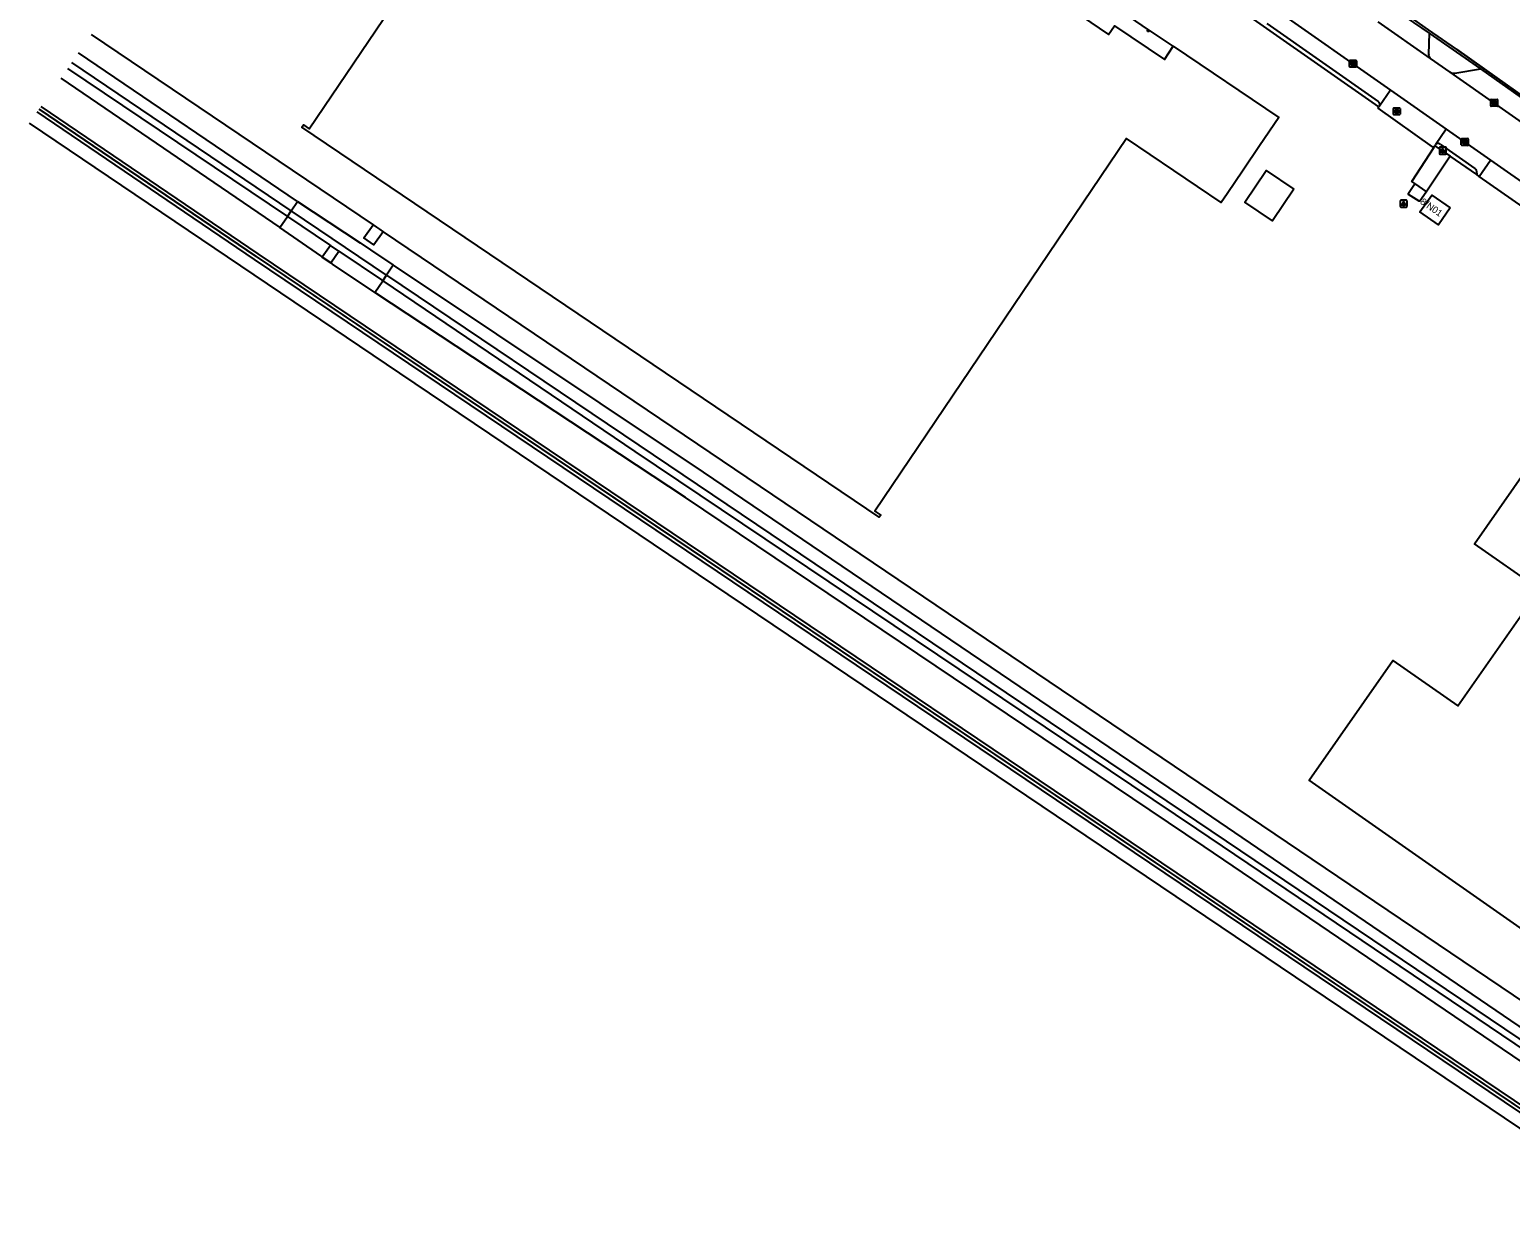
# Model space of a CAD drawing. Extents: x 155018 to 156648, y 383980 to 385733.
# Drawn here: x 155018.4 to 155235.9, y 384755.5 to 384931.8 of the extents above; entities that cross this region are included whole.
import ezdxf

# ---------------------------------------------------------------- set-up
doc = ezdxf.new("R2010")
doc.units = 0
for name, color, linetype in [('IMGEO_Brandkraan', 7, 'Continuous'), ('IMGEO_Groenvoorziening', 7, 'Continuous'), ('IMGEO_Hek', 7, 'Continuous'), ('IMGEO_Kademuur', 7, 'Continuous'), ('IMGEO_Kolk', 7, 'Continuous'), ('IMGEO_Lage_trafo', 7, 'Continuous'), ('IMGEO_Lichtpunt', 7, 'Continuous'), ('IMGEO_Oever', 7, 'Continuous'), ('IMGEO_Pand', 7, 'Continuous'), ('IMGEO_Pand_nummerreeks', 7, 'Continuous'), ('IMGEO_Pand_overbouw', 7, 'Continuous'), ('IMGEO_Parkeervlak_open', 7, 'Continuous'), ('IMGEO_Rijbaan_lokaal_gesloten', 7, 'Continuous'), ('IMGEO_Rijbaan_lokaal_open', 7, 'Continuous'), ('IMGEO_Terreindeel_onvherhard', 7, 'Continuous'), ('IMGEO_Voetpad_open', 7, 'Continuous'), ('IMGEO_Waterloop', 7, 'Continuous')]:
    doc.layers.add(name, color=color, linetype=linetype)

msp = doc.modelspace()

# ---------------------------------------------------------------- linework, layer by layer
at = {"layer": 'IMGEO_Brandkraan'}
for p, q in [((155218.71, 384919.32), (155218.71, 384920.18)), ((155218.78, 384920.25), (155219.64, 384920.25)), ((155219.2, 384920.03), (155219.22, 384920.03)), ((155219.71, 384920.18), (155219.71, 384919.32)), ((155219.64, 384919.25), (155218.78, 384919.25)), ((155219.22, 384919.47), (155219.2, 384919.47))]:
    msp.add_line(p, q, dxfattribs=at)
for points in [[(155218.71, 384919.32), (155218.71, 384920.18)], [(155218.78, 384920.25), (155219.64, 384920.25)], [(155219.06, 384919.95), (155219.06, 384919.55), (155219.27, 384919.55)], [(155219.29, 384919.95), (155219.06, 384919.95)], [(155219.24, 384919.87), (155219.18, 384919.87), (155219.18, 384919.79)], [(155219.71, 384920.18), (155219.71, 384919.32)], [(155219.64, 384919.25), (155218.78, 384919.25)], [(155219.18, 384919.79), (155219.24, 384919.79)], [(155219.25, 384919.72), (155219.18, 384919.72), (155219.18, 384919.64)], [(155219.18, 384919.64), (155219.25, 384919.64)]]:
    msp.add_lwpolyline(points, dxfattribs=at)
for centre, radius, start, end in [((155218.79, 384920.17), 0.0765, 91.552, 178.448), ((155218.79, 384920.17), 0.0765, 91.552, 178.448), ((155219.24, 384919.83), 0.0379, 267.8285, 90.9355), ((155219.29, 384919.8), 0.145, 59.4692, 91.5367), ((155219.32, 384919.85), 0.0922, 285.5137, 58.1501), ((155219.63, 384920.17), 0.0765, 1.552, 88.448), ((155219.63, 384920.17), 0.0765, 1.552, 88.448), ((155218.79, 384919.33), 0.0765, 181.552, 268.448), ((155218.79, 384919.33), 0.0765, 181.552, 268.448), ((155219.25, 384919.68), 0.0404, 269.8759, 90.5077), ((155219.28, 384919.8), 0.251, 268.6676, 293.5347), ((155219.32, 384919.66), 0.105, 301.3115, 78.989), ((155219.63, 384919.33), 0.0765, 271.552, 358.448), ((155219.63, 384919.33), 0.0765, 271.552, 358.448)]:
    msp.add_arc(centre, radius, start, end, dxfattribs=at)
for centre, major_axis, ratio, start_param, end_param in [((155219.2, 384919.75), (-0.387, 0.002), 0.722429, 4.712389, 7.853982), ((155219.22, 384919.75), (-0.39, 0.002), 0.717154, 1.570796, 4.712389)]:
    msp.add_ellipse(centre, major_axis=major_axis, ratio=ratio, start_param=start_param, end_param=end_param, dxfattribs=at)
at = {"layer": 'IMGEO_Groenvoorziening'}
for points in [[(155027.41, 384931.04), (155068.82, 384903.06)], [(155057.73, 384906.51), (155025.53, 384928.34)], [(155022.94, 384924.62), (155055.13, 384902.68)], [(155476.25, 384612.78), (155452.62, 384628.74), (155051.94, 384898.82), (155020.06, 384920.48)], [(155462.06, 384621.17), (155273.61, 384748.19), (155051.38, 384897.99), (155019.49, 384919.66)], [(155057.73, 384906.51), (155066.91, 384900.45), (155068.45, 384899.42), (155071.7, 384897.2), (155071.77, 384897.16)], [(155061.36, 384898.34), (155061.22, 384898.44), (155061.13, 384898.5), (155055.13, 384902.68)], [(155070.29, 384902.07), (155068.92, 384900.13), (155067.44, 384901.17), (155068.82, 384903.06)], [(155068.82, 384903.06), (155069.31, 384902.73), (155069.77, 384902.42), (155070.29, 384902.07)], [(155070.29, 384902.07), (155295.33, 384750), (155489.59, 384618.73)], [(155062.61, 384897.47), (155061.36, 384898.34)], [(155069.08, 384893.11), (155062.85, 384897.31), (155062.74, 384897.39), (155062.61, 384897.47)], [(155071.77, 384897.16), (155117.29, 384866.73), (155188.59, 384818.4), (155275.37, 384759.29), (155397.34, 384677)], [(155479.94, 384619.28), (155479.94, 384619.27), (155479.35, 384618.47), (155478.16, 384618.25), (155475.96, 384619.11), (155396.84, 384672.62), (155274.45, 384755.08), (155190.89, 384811.75), (155114.7, 384863.03), (155069.08, 384893.11)]]:
    msp.add_lwpolyline(points, dxfattribs=at)
at = {"layer": 'IMGEO_Hek'}
for points in [[(155227.99, 384928.88), (155232.07, 384925.99)], [(155232.07, 384925.99), (155247.24, 384915.22)], [(155051.66, 384898.4), (155019.78, 384920.07)], [(155224.48, 384914.55), (155216.48, 384920.23)], [(155051.66, 384898.4), (155112.43, 384857.45), (155113.3, 384856.85), (155273.89, 384748.61)]]:
    msp.add_lwpolyline(points, dxfattribs=at)
at = {"layer": 'IMGEO_Kademuur'}
msp.add_lwpolyline([(155062.55, 384900.04), (155061.36, 384898.34), (155062.61, 384897.47), (155063.81, 384899.19)], dxfattribs=at)
at = {"layer": 'IMGEO_Kolk'}
for p, q in [((155212.26, 384926.33), (155212.26, 384927.18)), ((155212.34, 384927.26), (155213.19, 384927.26)), ((155212.75, 384927.04), (155212.78, 384927.04)), ((155212.77, 384926.48), (155212.75, 384926.48)), ((155213.27, 384927.18), (155213.27, 384926.33)), ((155213.19, 384926.26), (155212.34, 384926.26)), ((155233.03, 384920.58), (155233.03, 384921.43)), ((155233.1, 384921.5), (155233.95, 384921.5)), ((155233.95, 384920.5), (155233.1, 384920.5)), ((155233.51, 384921.28), (155233.54, 384921.28)), ((155233.54, 384920.72), (155233.51, 384920.72)), ((155234.03, 384921.43), (155234.03, 384920.58)), ((155228.69, 384914.82), (155228.69, 384915.67)), ((155228.77, 384915.75), (155229.62, 384915.75)), ((155229.18, 384915.53), (155229.2, 384915.53)), ((155229.69, 384915.67), (155229.69, 384914.82)), ((155229.62, 384914.75), (155228.77, 384914.75)), ((155229.2, 384914.97), (155229.18, 384914.97))]:
    msp.add_line(p, q, dxfattribs=at)
for points in [[(155212.26, 384926.33), (155212.26, 384927.18)], [(155212.34, 384927.26), (155213.19, 384927.26)], [(155212.58, 384926.96), (155212.71, 384926.96), (155212.71, 384926.8), (155212.84, 384926.96), (155213, 384926.96), (155212.86, 384926.81), (155213.01, 384926.56), (155212.86, 384926.56), (155212.77, 384926.72), (155212.71, 384926.65), (155212.71, 384926.56), (155212.58, 384926.56), (155212.58, 384926.96)], [(155213.27, 384927.18), (155213.27, 384926.33)], [(155213.19, 384926.26), (155212.34, 384926.26)], [(155233.03, 384920.58), (155233.03, 384921.43)], [(155233.1, 384921.5), (155233.95, 384921.5)], [(155233.95, 384920.5), (155233.1, 384920.5)], [(155233.35, 384921.2), (155233.47, 384921.2), (155233.47, 384921.05), (155233.6, 384921.2), (155233.76, 384921.2), (155233.62, 384921.05), (155233.77, 384920.8), (155233.62, 384920.8), (155233.53, 384920.97), (155233.47, 384920.9), (155233.47, 384920.8), (155233.35, 384920.8), (155233.35, 384921.2)], [(155234.03, 384921.43), (155234.03, 384920.58)], [(155228.69, 384914.82), (155228.69, 384915.67)], [(155228.77, 384915.75), (155229.62, 384915.75)], [(155229.69, 384915.67), (155229.69, 384914.82)], [(155229.62, 384914.75), (155228.77, 384914.75)], [(155229.01, 384915.45), (155229.14, 384915.45), (155229.14, 384915.29), (155229.26, 384915.45), (155229.43, 384915.45), (155229.28, 384915.3), (155229.44, 384915.05), (155229.28, 384915.05), (155229.2, 384915.21), (155229.14, 384915.14), (155229.14, 384915.05), (155229.01, 384915.05), (155229.01, 384915.45)]]:
    msp.add_lwpolyline(points, dxfattribs=at)
for centre, start, end in [((155212.34, 384927.18), 91.552, 178.448), ((155212.34, 384927.18), 91.552, 178.448), ((155213.19, 384927.18), 1.552, 88.448), ((155213.19, 384927.18), 1.552, 88.448), ((155212.34, 384926.33), 181.552, 268.448), ((155212.34, 384926.33), 181.552, 268.448), ((155213.19, 384926.33), 271.552, 358.448), ((155213.19, 384926.33), 271.552, 358.448), ((155233.1, 384921.43), 91.552, 178.448), ((155233.1, 384921.43), 91.552, 178.448), ((155233.1, 384920.58), 181.552, 268.448), ((155233.1, 384920.58), 181.552, 268.448), ((155233.95, 384921.43), 1.552, 88.448), ((155233.95, 384921.43), 1.552, 88.448), ((155233.95, 384920.58), 271.552, 358.448), ((155233.95, 384920.58), 271.552, 358.448), ((155228.77, 384915.67), 91.552, 178.448), ((155228.77, 384915.67), 91.552, 178.448), ((155229.62, 384915.67), 1.552, 88.448), ((155229.62, 384915.67), 1.552, 88.448), ((155228.77, 384914.82), 181.552, 268.448), ((155228.77, 384914.82), 181.552, 268.448), ((155229.62, 384914.82), 271.552, 358.448), ((155229.62, 384914.82), 271.552, 358.448)]:
    msp.add_arc(centre, 0.0765, start, end, dxfattribs=at)
for centre, major_axis, ratio, start_param, end_param in [((155212.75, 384926.76), (-0.387, 0.002), 0.722429, 4.712389, 7.853982), ((155212.78, 384926.76), (-0.39, 0.002), 0.717154, 1.570796, 4.712389), ((155233.51, 384921), (-0.387, 0.002), 0.722429, 4.712389, 7.853982), ((155233.54, 384921), (-0.39, 0.002), 0.717154, 1.570796, 4.712389), ((155229.18, 384915.25), (-0.387, 0.002), 0.722429, 4.712389, 7.853982), ((155229.2, 384915.25), (-0.39, 0.002), 0.717154, 1.570796, 4.712389)]:
    msp.add_ellipse(centre, major_axis=major_axis, ratio=ratio, start_param=start_param, end_param=end_param, dxfattribs=at)
at = {"layer": 'IMGEO_Lage_trafo'}
for points in [[(155223.51, 384907.87), (155222.62, 384906.56), (155222.49, 384906.53), (155220.95, 384907.55), (155220.91, 384907.73), (155221.82, 384909.03), (155221.99, 384909.07)], [(155223.51, 384907.87), (155223.46, 384908.04), (155221.99, 384909.07)]]:
    msp.add_lwpolyline(points, dxfattribs=at)
at = {"layer": 'IMGEO_Lichtpunt'}
for p, q in [((155225.47, 384914.38), (155225.47, 384913.57)), ((155225.47, 384914.38), (155225.47, 384913.57)), ((155226.38, 384914.47), (155225.57, 384914.47)), ((155226.38, 384914.47), (155225.57, 384914.47)), ((155225.57, 384913.48), (155226.38, 384913.48)), ((155225.57, 384913.48), (155226.38, 384913.48)), ((155226.47, 384913.57), (155226.47, 384914.38)), ((155226.47, 384913.57), (155226.47, 384914.38)), ((155219.73, 384906.59), (155219.73, 384905.79)), ((155219.73, 384906.59), (155219.73, 384905.79)), ((155220.63, 384906.69), (155219.83, 384906.69)), ((155220.63, 384906.69), (155219.83, 384906.69)), ((155219.83, 384905.69), (155220.63, 384905.69)), ((155219.83, 384905.69), (155220.63, 384905.69)), ((155220.73, 384905.79), (155220.73, 384906.59)), ((155220.73, 384905.79), (155220.73, 384906.59))]:
    msp.add_line(p, q, dxfattribs=at)
for points in [[(155225.85, 384914.04), (155225.89, 384914.02), (155225.7, 384913.75), (155225.66, 384913.78), (155225.85, 384914.04)], [(155225.95, 384914), (155226, 384914), (155226, 384913.67), (155225.95, 384913.67), (155225.95, 384914)], [(155226.06, 384914.02), (155226.1, 384914.04), (155226.28, 384913.78), (155226.25, 384913.75), (155226.06, 384914.02)], [(155220.11, 384906.26), (155220.14, 384906.23), (155219.96, 384905.97), (155219.92, 384905.99), (155220.11, 384906.26)], [(155220.21, 384906.21), (155220.25, 384906.21), (155220.25, 384905.89), (155220.21, 384905.89), (155220.21, 384906.21)], [(155220.32, 384906.23), (155220.36, 384906.26), (155220.54, 384905.99), (155220.5, 384905.97), (155220.32, 384906.23)]]:
    msp.add_lwpolyline(points, dxfattribs=at)
for centre in [(155225.97, 384914.18), (155220.23, 384906.39)]:
    msp.add_circle(centre, 0.0994, dxfattribs=at)
for centre, start, end in [((155225.57, 384914.38), 90, 180), ((155225.57, 384914.38), 90, 180), ((155225.57, 384913.57), 180, 270), ((155225.57, 384913.57), 180, 270), ((155226.38, 384914.38), 0, 90), ((155226.38, 384914.38), 0, 90), ((155226.38, 384913.57), 270, 0), ((155226.38, 384913.57), 270, 360), ((155219.83, 384906.59), 90, 180), ((155219.83, 384906.59), 90, 180), ((155219.83, 384905.79), 180, 270), ((155219.83, 384905.79), 180, 270), ((155220.63, 384906.59), 0, 90), ((155220.63, 384906.59), 0, 90), ((155220.63, 384905.79), 270, 0), ((155220.63, 384905.79), 270, 360)]:
    msp.add_arc(centre, 0.0946, start, end, dxfattribs=at)
at = {"layer": 'IMGEO_Oever'}
for points in [[(155056.8, 384905.14), (155057.73, 384906.51)], [(155055.13, 384902.68), (155056.23, 384904.3)], [(155062.55, 384900.04), (155061.36, 384898.34)], [(155062.61, 384897.47), (155063.81, 384899.19)], [(155071.77, 384897.16), (155070.79, 384895.69)], [(155069.08, 384893.11), (155070.24, 384894.86)]]:
    msp.add_lwpolyline(points, dxfattribs=at)
at = {"layer": 'IMGEO_Pand'}
for points in [[(155176.85, 384931.04), (155177.73, 384932.32), (155185.07, 384927.38), (155186.34, 384929.31), (155201.86, 384918.83), (155199.06, 384914.69), (155196.65, 384911.13), (155194.29, 384907.65), (155193.41, 384906.34), (155179.51, 384915.75), (155142.55, 384860.99), (155143.39, 384860.41), (155143.18, 384860.1), (155058.34, 384917.41), (155058.58, 384917.77), (155059.42, 384917.18), (155100.78, 384978.3)], [(155172.88, 384933.73), (155176.85, 384931.04)], [(155204.09, 384908.31), (155200.94, 384903.66), (155196.87, 384906.42), (155200.02, 384911.07), (155204.09, 384908.31)], [(155227.07, 384905.56), (155225.34, 384903.08), (155222.58, 384904.99), (155224.36, 384907.42), (155227.07, 384905.56)], [(155307.85, 384846.47), (155308.08, 384846.3), (155307.16, 384844.98), (155311.87, 384841.65), (155312.84, 384843), (155313.12, 384842.89), (155325.2, 384834.41), (155316.62, 384822.15), (155331.37, 384811.8), (155328.5, 384807.71), (155294.79, 384759.56), (155206.34, 384821.5), (155218.64, 384839.08), (155228.19, 384832.39), (155240.18, 384849.52), (155230.62, 384856.2), (155240.04, 384869.66), (155242.91, 384873.76), (155277.33, 384849.67), (155285.97, 384861.91), (155307.85, 384846.47)]]:
    msp.add_lwpolyline(points, dxfattribs=at)
at = {"layer": 'IMGEO_Pand_overbouw'}
msp.add_lwpolyline([(155172.88, 384933.73), (155176.85, 384931.04), (155177.73, 384932.32), (155185.07, 384927.38), (155186.34, 384929.31), (155182.83, 384931.67), (155182.83, 384931.66), (155182.84, 384931.65), (155182.84, 384931.64), (155182.85, 384931.63), (155182.85, 384931.62), (155182.85, 384931.61), (155182.85, 384931.6), (155182.85, 384931.59), (155182.85, 384931.58), (155182.84, 384931.57), (155182.84, 384931.55), (155182.84, 384931.54), (155182.83, 384931.53), (155182.83, 384931.53), (155182.82, 384931.52), (155182.81, 384931.51), (155182.8, 384931.5), (155182.79, 384931.49), (155182.79, 384931.49), (155182.77, 384931.48), (155182.77, 384931.48), (155182.75, 384931.48), (155182.74, 384931.47), (155182.73, 384931.47), (155182.72, 384931.47), (155182.71, 384931.47), (155182.7, 384931.47), (155182.69, 384931.48), (155182.68, 384931.48), (155182.67, 384931.48), (155182.66, 384931.49), (155182.65, 384931.49), (155182.64, 384931.5), (155182.63, 384931.51), (155182.62, 384931.52), (155182.62, 384931.53), (155182.61, 384931.54), (155182.61, 384931.55), (155182.6, 384931.56), (155182.6, 384931.57), (155182.6, 384931.58), (155182.6, 384931.59), (155182.6, 384931.6), (155182.6, 384931.61), (155182.6, 384931.62), (155182.6, 384931.63), (155182.6, 384931.64), (155182.61, 384931.65), (155182.61, 384931.66), (155182.62, 384931.67), (155182.63, 384931.68), (155182.63, 384931.69), (155182.64, 384931.7), (155182.65, 384931.7), (155182.66, 384931.71), (155182.67, 384931.72), (155182.68, 384931.72), (155182.69, 384931.72), (155182.7, 384931.72), (155182.71, 384931.73), (155182.72, 384931.73), (155182.74, 384931.73), (155178.99, 384934.25)], dxfattribs=at)
at = {"layer": 'IMGEO_Parkeervlak_open'}
msp.add_lwpolyline([(155231.32, 384910.2), (155230.96, 384910.46)], dxfattribs=at)
at = {"layer": 'IMGEO_Rijbaan_lokaal_gesloten'}
for points in [[(155200.81, 384935.12), (155218.31, 384922.86)], [(155224.17, 384927.53), (155216.5, 384932.9)], [(155227.05, 384925.51), (155224.17, 384927.53)], [(155247.68, 384911.07), (155227.05, 384925.51)], [(155218.31, 384922.86), (155226.48, 384917.15)], [(155460.95, 384619.54), (155267.44, 384750), (155252.61, 384760), (155072.77, 384881.27), (155018.36, 384918.03)], [(155226.48, 384917.15), (155233, 384912.58)], [(155233, 384912.58), (155239.47, 384908.04)]]:
    msp.add_lwpolyline(points, dxfattribs=at)
at = {"layer": 'IMGEO_Rijbaan_lokaal_open'}
for points in [[(155247.24, 384915.22), (155232.07, 384925.99), (155227.99, 384928.88), (155223.85, 384931.75), (155220.05, 384934.4), (155190.84, 384954.67), (155188.93, 384956.01), (155183.12, 384960.07), (155179.96, 384962.28), (155172.39, 384967.57), (155170.21, 384969.31), (155168.5, 384970.51), (155163.31, 384974.14), (155155.32, 384979.58), (155155.1, 384979.41)], [(155220.57, 384933.53), (155223.98, 384931.26)], [(155223.98, 384931.26), (155223.86, 384928.17)], [(155223.98, 384931.26), (155231.51, 384925.99)], [(155231.51, 384925.99), (155247.25, 384914.87)], [(155218.31, 384922.86), (155216.66, 384920.5)], [(155224.68, 384914.48), (155224.48, 384914.55), (155216.48, 384920.23), (155216.59, 384920.39)], [(155216.66, 384920.5), (155216.59, 384920.39)], [(155226.48, 384917.15), (155224.89, 384914.82)], [(155224.68, 384914.48), (155224.82, 384914.7)], [(155224.82, 384914.7), (155224.89, 384914.82)], [(155231.32, 384910.2), (155233, 384912.58)], [(155237.77, 384905.65), (155231.32, 384910.2)]]:
    msp.add_lwpolyline(points, dxfattribs=at)
msp.add_arc((155224.97, 384928.3), 1.11, 186.9128, 224.2765, dxfattribs=at)
at = {"layer": 'IMGEO_Terreindeel_onvherhard'}
msp.add_lwpolyline([(155019.78, 384920.07), (155051.66, 384898.4), (155273.89, 384748.61), (155462.32, 384621.41)], dxfattribs=at)
at = {"layer": 'IMGEO_Voetpad_open'}
for points in [[(155216.59, 384920.39), (155102.88, 385000), (155101.2, 385001.18)], [(155200.14, 384932.65), (155216.5, 384921.19)], [(155227.75, 384925.34), (155231.51, 384925.99)], [(155221.99, 384909.07), (155221.44, 384909.46), (155224.68, 384914.48)], [(155224.82, 384914.7), (155227.04, 384913.16)], [(155225.6, 384914.92), (155230.66, 384911.36)], [(155227.04, 384913.16), (155223.51, 384907.87)], [(155230.96, 384910.46), (155227.04, 384913.16)], [(155230.99, 384910.65), (155230.96, 384910.46)]]:
    msp.add_lwpolyline(points, dxfattribs=at)
for centre, radius, start, end in [((155227.64, 384926.4), 1.06, 236.6229, 276.1184), ((155216.24, 384920.76), 0.5, 327.9229, 58.5858), ((155225.29, 384914.55), 0.481, 50.5038, 145.5506), ((155230.17, 384910.7), 0.821, 356.4526, 53.1285)]:
    msp.add_arc(centre, radius, start, end, dxfattribs=at)
at = {"layer": 'IMGEO_Waterloop'}
for points in [[(155056.8, 384905.14), (155024.56, 384926.95)], [(155023.93, 384926.04), (155056.23, 384904.3)], [(155056.23, 384904.3), (155056.8, 384905.14)], [(155070.79, 384895.69), (155056.8, 384905.14)], [(155056.23, 384904.3), (155062.41, 384900.14), (155062.55, 384900.04)], [(155063.81, 384899.19), (155062.55, 384900.04)], [(155063.81, 384899.19), (155063.93, 384899.11), (155070.06, 384894.98), (155070.24, 384894.86)], [(155070.24, 384894.86), (155070.79, 384895.69)], [(155070.24, 384894.86), (155107.27, 384869.77), (155189.8, 384814.33), (155275.77, 384756.26), (155396.16, 384675.24)], [(155070.79, 384895.69), (155107.86, 384870.72), (155189.77, 384815.43), (155286.77, 384750.06), (155396.63, 384675.94)]]:
    msp.add_lwpolyline(points, dxfattribs=at)

# ---------------------------------------------------------------- texts
at = {"layer": 'IMGEO_Pand_nummerreeks'}
msp.add_text('8/N01', height=1, rotation=325.3327, dxfattribs=at).set_placement((155222.55, 384906.26))

doc.saveas('drawing.dxf')
